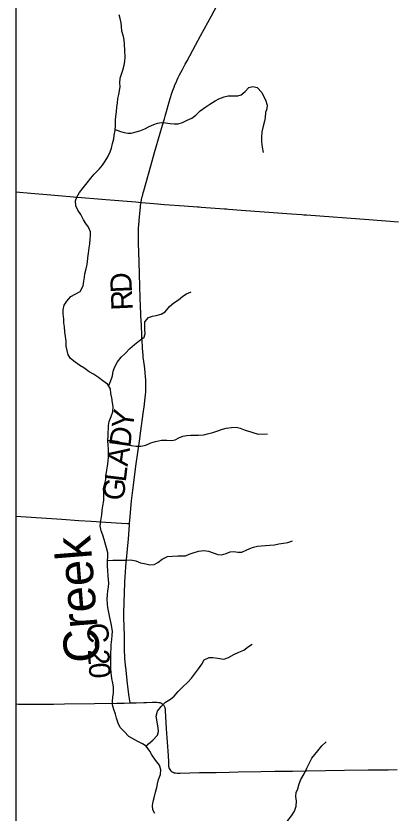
# Model space of a CAD drawing. Extents: x 0 to 1052, y -194 to 246.
# Drawn here: x 1.982 to 2.989, y 15.72 to 17.846 of the extents above; entities that cross this region are included whole.
import ezdxf

# ---------------------------------------------------------------- set-up
doc = ezdxf.new("R2010")
doc.units = 0
for name, color, linetype in [('GM_X_Corporation', 7, 'Continuous'), ('GM_X_County_Road', 7, 'Continuous'), ('GM_X_County_Road_Text', 7, 'Continuous'), ('GM_X_Minor_River', 7, 'Continuous'), ('GM_X_Minor_River_Text', 7, 'Continuous'), ('GM_X_Township_Road', 7, 'Continuous')]:
    doc.layers.add(name, color=color, linetype=linetype)

msp = doc.modelspace()

# ---------------------------------------------------------------- linework, layer by layer
at = {"layer": 'GM_X_Corporation'}
msp.add_lwpolyline([(1.9822, 21.0055), (1.9822, 14.2055)], dxfattribs=at)
msp.add_lwpolyline([(1.9822, 21.0055), (1.9822, 14.2055)], dxfattribs=at)
at = {"layer": 'GM_X_County_Road'}
for points in [[(2.316, 17.3485), (2.3163, 17.3504), (2.3172, 17.3549), (2.3185, 17.3614), (2.3195, 17.3654), (2.3206, 17.3699), (2.3219, 17.3746), (2.3233, 17.3795), (2.3421, 17.4458), (2.3522, 17.4817), (2.3671, 17.5331), (2.3733, 17.5545), (2.3784, 17.5719), (2.3793, 17.5748), (2.3803, 17.5784), (2.3939, 17.6255), (2.3983, 17.6398), (2.4002, 17.6454), (2.4023, 17.6516), (2.4042, 17.6563), (2.4066, 17.6626), (2.4094, 17.6687), (2.4125, 17.6757), (2.4155, 17.6819), (2.4191, 17.6891), (2.4221, 17.6949), (2.4256, 17.7016), (2.431, 17.7117), (2.4341, 17.7175), (2.4391, 17.7267), (2.4616, 17.7679), (2.4748, 17.7926), (2.5041, 17.8459), (2.5187, 17.8727)], [(1.9822, 17.3766), (2.0218, 17.3731), (2.0644, 17.3695), (2.0954, 17.3669), (2.1362, 17.3635), (2.2217, 17.3568), (2.3021, 17.3499), (2.316, 17.3485)], [(2.2855, 16.4918), (2.2871, 16.5109), (2.291, 16.5524), (2.2943, 16.5814), (2.2987, 16.6159), (2.3025, 16.6449), (2.3118, 16.712), (2.3155, 16.739), (2.3216, 16.7852), (2.325, 16.8096), (2.3255, 16.8135), (2.3259, 16.8174), (2.3273, 16.8292), (2.3277, 16.8333), (2.3281, 16.8373), (2.3284, 16.8408), (2.3287, 16.8444), (2.3289, 16.8501), (2.3292, 16.8555), (2.3291, 16.861), (2.3291, 16.866), (2.3289, 16.8702), (2.3287, 16.874), (2.3285, 16.8772), (2.3282, 16.8812), (2.3278, 16.8861), (2.3272, 16.892), (2.3268, 16.8957), (2.3249, 16.9123), (2.3221, 16.9361), (2.3217, 16.9395), (2.3213, 16.9435), (2.3209, 16.9483), (2.3205, 16.9525), (2.3202, 16.957), (2.3198, 16.964), (2.3195, 16.9694), (2.3192, 16.9736), (2.3171, 17.0198), (2.3169, 17.0239), (2.3167, 17.03), (2.314, 17.0934), (2.3119, 17.1568), (2.3109, 17.1903), (2.3094, 17.2406), (2.3089, 17.2661), (2.309, 17.2694), (2.309, 17.273), (2.3092, 17.278), (2.3095, 17.2823), (2.3099, 17.2874), (2.311, 17.3003), (2.3145, 17.3371), (2.3149, 17.3405), (2.3154, 17.3444), (2.316, 17.3485)], [(2.316, 17.3485), (2.3281, 17.3472), (2.3504, 17.3454), (2.3783, 17.3435), (2.431, 17.3394), (2.4666, 17.3368), (2.4713, 17.3364), (2.4768, 17.336), (2.5384, 17.3315), (2.5438, 17.3311), (2.549, 17.3307), (2.5834, 17.3282), (2.6447, 17.3235), (2.7173, 17.3184), (2.7455, 17.3161), (2.7507, 17.3157), (2.7575, 17.3152), (2.9236, 17.303), (3.0035, 17.2967)], [(2.2872, 16.0135), (2.2847, 16.0299), (2.2826, 16.0435), (2.2798, 16.0657), (2.2751, 16.1086), (2.2747, 16.112), (2.2744, 16.1155), (2.273, 16.1319), (2.2728, 16.1358), (2.2726, 16.1394), (2.2724, 16.143), (2.2721, 16.1474), (2.272, 16.1517), (2.2719, 16.1556), (2.2718, 16.1592), (2.2718, 16.1627), (2.2717, 16.167), (2.2715, 16.1909), (2.2709, 16.2182), (2.2703, 16.2406), (2.2702, 16.2568), (2.2707, 16.2791), (2.272, 16.3096), (2.274, 16.354), (2.2742, 16.358), (2.2745, 16.3614), (2.2756, 16.3772), (2.2822, 16.4515), (2.2852, 16.488), (2.2855, 16.4918)], [(1.9822, 16.0107), (1.9892, 16.0104), (2.0483, 16.0099), (2.0824, 16.0103), (2.1116, 16.0107), (2.1918, 16.0122), (2.2514, 16.0128), (2.2713, 16.0131), (2.2872, 16.0135)], [(2.2872, 16.0135), (2.3029, 16.0139), (2.3234, 16.0145), (2.3309, 16.0146), (2.347, 16.0151), (2.3582, 16.0152), (2.3624, 16.0149), (2.3661, 16.0143), (2.3689, 16.0135), (2.3716, 16.0122), (2.374, 16.0105), (2.3756, 16.0088), (2.377, 16.007), (2.378, 16.0052), (2.3789, 16.0033), (2.3794, 16.0016), (2.3798, 16), (2.3802, 15.998), (2.3804, 15.9959), (2.3806, 15.9932), (2.383, 15.9441), (2.388, 15.8735), (2.3889, 15.8567), (2.3894, 15.8473), (2.3897, 15.845), (2.3901, 15.8423), (2.3906, 15.8407), (2.3913, 15.8386), (2.3929, 15.8358), (2.3945, 15.8337), (2.3963, 15.8318), (2.3989, 15.8299), (2.4018, 15.8284), (2.4048, 15.8273), (2.4079, 15.8266), (2.4123, 15.8262), (2.4205, 15.826), (2.446, 15.8267), (2.4721, 15.8275), (2.5162, 15.8283), (2.5516, 15.8292), (2.5752, 15.8296), (2.6361, 15.8303), (2.6727, 15.8312), (2.7199, 15.8316), (2.7578, 15.8324), (2.8082, 15.833), (2.8591, 15.8339), (2.9219, 15.8346), (2.9467, 15.835), (2.9759, 15.8354), (2.9995, 15.8359)]]:
    msp.add_lwpolyline(points, dxfattribs=at)
at = {"layer": 'GM_X_Minor_River'}
for points in [[(2.2143, 16.873), (2.2022, 16.8819), (2.1891, 16.8904), (2.1777, 16.897), (2.1634, 16.9071), (2.1529, 16.9137), (2.1405, 16.9222), (2.1277, 16.9322), (2.1218, 16.9418), (2.1185, 16.9532), (2.1164, 16.9654), (2.1158, 16.9787), (2.1148, 16.9912), (2.1123, 17.0034), (2.1114, 17.0167), (2.1104, 17.0273), (2.1097, 17.0368), (2.1084, 17.0513), (2.1082, 17.0623), (2.111, 17.0744), (2.1176, 17.0849), (2.1288, 17.0977), (2.1399, 17.104), (2.1533, 17.1114), (2.1615, 17.1261), (2.1635, 17.1386), (2.1648, 17.1489), (2.1661, 17.1583), (2.1685, 17.1682), (2.1717, 17.1799), (2.1729, 17.1894), (2.1739, 17.2008), (2.1755, 17.2133), (2.178, 17.2277), (2.1797, 17.2383), (2.1806, 17.25), (2.1811, 17.2603), (2.1813, 17.2701), (2.1761, 17.2824), (2.1683, 17.2927), (2.1627, 17.3026), (2.1553, 17.3168), (2.1471, 17.3283), (2.1419, 17.3394), (2.1413, 17.3527), (2.1449, 17.3625), (2.1519, 17.3753), (2.1616, 17.3873), (2.1727, 17.4005), (2.1824, 17.4129), (2.1909, 17.4238), (2.204, 17.4376), (2.2129, 17.4478), (2.2202, 17.4583), (2.2276, 17.4704), (2.2339, 17.4832), (2.2371, 17.4934), (2.2403, 17.5059), (2.2435, 17.518), (2.2447, 17.5278), (2.2472, 17.5407), (2.2477, 17.5536), (2.2483, 17.568), (2.2492, 17.5775), (2.2501, 17.5904), (2.2518, 17.6037), (2.2531, 17.6132), (2.2544, 17.6257), (2.2568, 17.6363), (2.2589, 17.6461), (2.2602, 17.6575), (2.2595, 17.667), (2.2605, 17.6799), (2.2636, 17.6905), (2.2672, 17.7018), (2.2708, 17.7147), (2.2728, 17.7249), (2.2734, 17.7374), (2.2728, 17.753), (2.2723, 17.772), (2.2709, 17.7815), (2.2688, 17.791), (2.2648, 17.8055), (2.2642, 17.8176), (2.2628, 17.8279), (2.2599, 17.8393), (2.2578, 17.8488)], [(2.2473, 17.5431), (2.2608, 17.5379), (2.2707, 17.5351), (2.2805, 17.5335), (2.29, 17.5337), (2.3026, 17.5366), (2.3129, 17.5399), (2.3266, 17.5446), (2.3373, 17.5509), (2.35, 17.5569), (2.3603, 17.5598), (2.3705, 17.5615), (2.3815, 17.561), (2.3937, 17.5593), (2.4043, 17.558), (2.4149, 17.5583), (2.4268, 17.5619), (2.4394, 17.5682), (2.4512, 17.5734), (2.4627, 17.5816), (2.4739, 17.5925), (2.4889, 17.6033), (2.4992, 17.6103), (2.5141, 17.6193), (2.5237, 17.6245), (2.5375, 17.6304), (2.5489, 17.6329), (2.5637, 17.633), (2.574, 17.6333), (2.5835, 17.6355), (2.5942, 17.6448), (2.6035, 17.6553), (2.6142, 17.6578), (2.6263, 17.655), (2.6383, 17.642), (2.6431, 17.6324), (2.6479, 17.6225), (2.6526, 17.6084), (2.6517, 17.5981), (2.6486, 17.5883), (2.6469, 17.5754), (2.6452, 17.5652), (2.6416, 17.5519), (2.6388, 17.5372), (2.6374, 17.5224), (2.6373, 17.5102), (2.639, 17.4962), (2.6422, 17.4821)], [(2.2296, 16.8588), (2.2348, 16.8708), (2.2395, 16.8856), (2.242, 16.8985), (2.2459, 16.9098), (2.2529, 16.9234), (2.263, 16.9361), (2.2749, 16.9466), (2.2865, 16.959), (2.2988, 16.9699), (2.3118, 16.9807), (2.3248, 16.9889), (2.3273, 16.9987), (2.3263, 17.0086), (2.326, 17.0196), (2.3265, 17.0299), (2.3362, 17.0415), (2.3469, 17.0455), (2.3568, 17.0469), (2.3697, 17.0506), (2.3801, 17.0565), (2.3924, 17.0711), (2.4036, 17.0805), (2.4158, 17.0891), (2.4274, 17.0984), (2.4377, 17.1047), (2.4499, 17.1099)], [(2.3526, 15.7187), (2.3474, 15.7286), (2.3464, 15.7396), (2.3488, 15.7502), (2.3512, 15.7604), (2.3549, 15.7756), (2.3584, 15.7881), (2.3601, 15.7979), (2.3629, 15.8089), (2.3676, 15.8229), (2.3693, 15.8346), (2.3653, 15.8472), (2.3545, 15.8606), (2.3452, 15.8748), (2.3396, 15.8847), (2.3299, 15.8978), (2.3197, 15.9047), (2.3077, 15.9106), (2.2839, 15.9242), (2.2712, 15.9372), (2.2607, 15.9484), (2.2552, 15.9598), (2.2508, 15.9728), (2.2483, 15.9839), (2.2435, 15.9964), (2.2402, 16.0083), (2.24, 16.0185), (2.2409, 16.0291), (2.2422, 16.0405), (2.2424, 16.0568), (2.2406, 16.0663), (2.2378, 16.0785), (2.2365, 16.0941), (2.2358, 16.1055), (2.2356, 16.115), (2.2358, 16.1271), (2.2355, 16.1378), (2.2357, 16.1476), (2.2362, 16.159), (2.2367, 16.1689), (2.238, 16.1829), (2.2393, 16.1935), (2.2395, 16.2053), (2.2359, 16.2258), (2.2327, 16.2411), (2.2303, 16.2548), (2.2278, 16.2677), (2.2268, 16.2772), (2.2258, 16.2894), (2.2263, 16.3023), (2.2276, 16.3117), (2.2293, 16.3235), (2.2298, 16.333), (2.2292, 16.3428), (2.2282, 16.3524), (2.2272, 16.3664), (2.2262, 16.3786), (2.2268, 16.3911), (2.2273, 16.4044), (2.2278, 16.4139), (2.2235, 16.4276), (2.2202, 16.4394), (2.2173, 16.4497), (2.2137, 16.4607), (2.2093, 16.4722), (2.2072, 16.4859), (2.2089, 16.4991), (2.2114, 16.515), (2.2123, 16.5264), (2.2143, 16.5393), (2.2164, 16.5533), (2.2167, 16.5734), (2.2161, 16.5856), (2.2189, 16.5954), (2.2225, 16.6098), (2.2234, 16.6227), (2.2247, 16.6348), (2.2268, 16.6451), (2.2285, 16.6587), (2.229, 16.6693), (2.2291, 16.6788), (2.2289, 16.6894), (2.2283, 16.7024), (2.2277, 16.7122), (2.2286, 16.727), (2.229, 16.7532), (2.2314, 16.7646), (2.2362, 16.7778), (2.2405, 16.7899), (2.2418, 16.8039), (2.2401, 16.8142), (2.238, 16.8275), (2.2351, 16.8389), (2.2341, 16.8511), (2.2267, 16.8637), (2.2143, 16.873)], [(2.2278, 16.7139), (2.2395, 16.7136), (2.252, 16.7119), (2.2675, 16.706), (2.2777, 16.7036), (2.2898, 16.7001), (2.3027, 16.6984), (2.3152, 16.6986), (2.3286, 16.7007), (2.3423, 16.707), (2.3545, 16.711), (2.3705, 16.7146), (2.3846, 16.714), (2.3979, 16.7131), (2.4074, 16.7149), (2.417, 16.7208), (2.428, 16.7248), (2.4379, 16.727), (2.4486, 16.728), (2.4695, 16.7277), (2.4832, 16.7287), (2.4931, 16.7312), (2.5076, 16.7352), (2.5209, 16.7392), (2.5331, 16.7436), (2.5434, 16.7465), (2.5571, 16.7478), (2.5697, 16.7488), (2.581, 16.7464), (2.5935, 16.7413), (2.6094, 16.7365), (2.62, 16.733), (2.6298, 16.7302), (2.6534, 16.7314)], [(2.2269, 16.3931), (2.2409, 16.3939), (2.2538, 16.3945), (2.2648, 16.3944), (2.2781, 16.3946), (2.2887, 16.3948), (2.3024, 16.3924), (2.3148, 16.3873), (2.3285, 16.3841), (2.3398, 16.382), (2.3513, 16.3827), (2.3612, 16.3878), (2.372, 16.3968), (2.3869, 16.4042), (2.3998, 16.4048), (2.4139, 16.4058), (2.4245, 16.4056), (2.4344, 16.4063), (2.4447, 16.4103), (2.455, 16.414), (2.4695, 16.4183), (2.484, 16.4204), (2.4965, 16.418), (2.5082, 16.414), (2.5214, 16.4097), (2.5309, 16.4088), (2.5435, 16.4117), (2.5542, 16.4165), (2.5641, 16.4171), (2.5743, 16.4154), (2.5853, 16.4161), (2.5964, 16.4209), (2.6063, 16.4257), (2.6162, 16.4286), (2.6269, 16.4319), (2.6364, 16.4329), (2.6482, 16.4335), (2.6596, 16.4341), (2.6722, 16.4351), (2.6836, 16.4376), (2.6958, 16.4393), (2.708, 16.4418), (2.7202, 16.4462)], [(2.33, 15.8977), (2.3357, 15.9041), (2.3476, 15.9139), (2.3596, 15.9274), (2.3623, 15.9372), (2.3613, 15.9475), (2.3596, 15.957), (2.3582, 15.968), (2.3568, 15.9783), (2.3597, 15.9911), (2.3697, 16.0043), (2.3816, 16.0152), (2.3947, 16.0233), (2.4043, 16.0312), (2.4154, 16.0436), (2.4274, 16.0567), (2.4409, 16.0691), (2.4509, 16.0799), (2.4613, 16.0935), (2.4694, 16.1044), (2.4787, 16.1172), (2.4846, 16.1289), (2.4976, 16.1344), (2.5078, 16.135), (2.5207, 16.1333), (2.5366, 16.1305), (2.5496, 16.1348), (2.5634, 16.143), (2.5772, 16.1485), (2.5905, 16.1541), (2.6024, 16.1638), (2.6124, 16.1705)], [(2.6665, 15.6507), (2.6701, 15.6618), (2.6771, 15.6746), (2.6875, 15.6802), (2.6978, 15.6891), (2.7082, 15.6996), (2.7175, 15.7124), (2.726, 15.7252), (2.7304, 15.7381), (2.731, 15.7513), (2.7289, 15.7643), (2.7297, 15.7745), (2.7341, 15.7843), (2.7384, 15.7979), (2.7428, 15.8093), (2.7513, 15.824), (2.7587, 15.8394), (2.7654, 15.8538), (2.772, 15.8658), (2.7797, 15.876), (2.7882, 15.8861), (2.7987, 15.8989), (2.8098, 15.9098)]]:
    msp.add_lwpolyline(points, dxfattribs=at)
at = {"layer": 'GM_X_Township_Road'}
msp.add_lwpolyline([(1.9822, 16.5121), (2.1044, 16.5035), (2.1503, 16.5005), (2.1825, 16.4983), (2.2222, 16.4959), (2.2637, 16.493), (2.2798, 16.4921), (2.2855, 16.4918)], dxfattribs=at)

# ---------------------------------------------------------------- texts
at = {"layer": 'GM_X_County_Road_Text'}
for s, rotation, p in [('D', 92.4013, (2.292, 17.1084)), ('R', 92.5377, (2.2941, 17.0618)), ('Y', 82.2116, (2.2936, 16.7422)), ('D', 82.2099, (2.2868, 16.6927)), ('A', 82.3201, (2.2801, 16.6431)), ('L', 83.1397, (2.2751, 16.6011)), ('G', 84.1248, (2.27, 16.5517)), ('C', 272.0105, (2.1719, 16.2263)), ('-', 272.088, (2.1735, 16.1795)), ('2', 272.4523, (2.1744, 16.1558)), ('0', 274.0888, (2.176, 16.1191))]:
    msp.add_text(s, height=0.0568, rotation=rotation, dxfattribs=at).set_placement(p)
at = {"layer": 'GM_X_Minor_River_Text'}
msp.add_text('Creek', height=0.0947, rotation=94.5882, dxfattribs=at).set_placement((2.2075, 16.1248))

doc.saveas('drawing.dxf')
